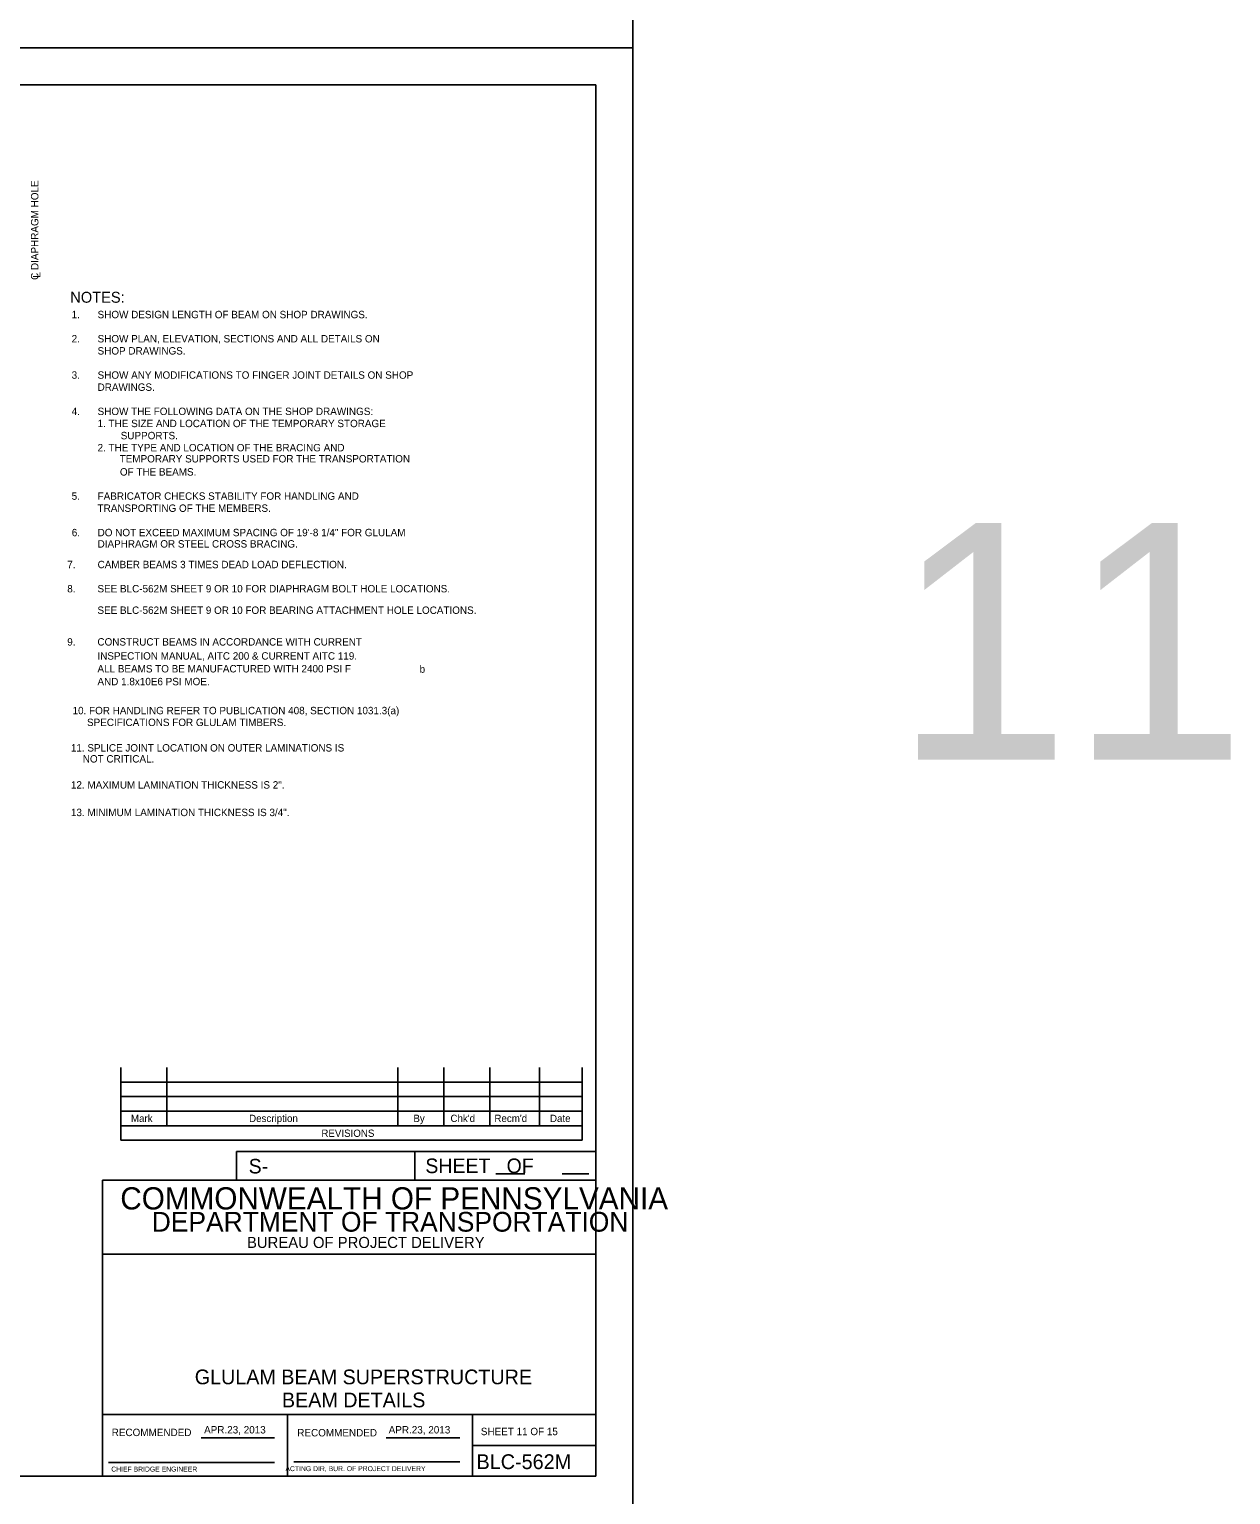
# Model space of a CAD drawing. Extents: x 638263 to 640391, y 293683 to 298655.
# Drawn here: x 639873 to 640360, y 296661 to 297255 of the extents above; entities that cross this region are included whole.
import ezdxf

# ---------------------------------------------------------------- set-up
doc = ezdxf.new("R2010")
doc.units = 0
for name, color, linetype in [('2', 7, 'Continuous'), ('4', 7, 'Continuous'), ('5', 7, 'Continuous'), ('PLT-BNDY', 7, 'Continuous')]:
    doc.layers.add(name, color=color, linetype=linetype)

msp = doc.modelspace()

# ---------------------------------------------------------------- linework, layer by layer
at = {"layer": '2'}
for p, q in [((639316.46, 297232.46), (640102.46, 297232.46)), ((640102.46, 297232.46), (640102.46, 296668.46)), ((639909.92, 296834.15), (639909.92, 296804.62)), ((639928.62, 296834.15), (639928.62, 296810.53)), ((640022.13, 296834.15), (640022.13, 296810.53)), ((640040.83, 296834.15), (640040.83, 296810.53)), ((640059.53, 296834.15), (640059.53, 296810.53)), ((640079.59, 296834.15), (640079.59, 296810.53)), ((640096.94, 296834.15), (640096.94, 296804.62)), ((640096.94, 296828.24), (639909.92, 296828.24)), ((640096.94, 296822.34), (639909.92, 296822.34)), ((640096.94, 296816.43), (639909.92, 296816.43)), ((640096.94, 296810.53), (639909.92, 296810.53)), ((640096.94, 296804.62), (639909.92, 296804.62)), ((640102.46, 296800.11), (639956.78, 296800.11)), ((639956.78, 296800.11), (639956.78, 296788.46)), ((640029.09, 296800.11), (640029.09, 296788.46)), ((640102.46, 296788.46), (639902.46, 296788.46)), ((639902.46, 296788.46), (639902.46, 296668.46)), ((640061.95, 296791), (640073.6, 296791)), ((640088.83, 296791), (640099.56, 296791)), ((640102.46, 296668.46), (640102.46, 296788.46)), ((640102.46, 296758.46), (639902.46, 296758.46)), ((640102.46, 296693.46), (639902.46, 296693.46)), ((639977.46, 296668.46), (639977.46, 296693.46)), ((640052.46, 296693.46), (640052.46, 296668.46)), ((639942.42, 296683.96), (639972.19, 296683.96)), ((640017.42, 296683.96), (640047.33, 296683.96)), ((640052.46, 296680.96), (640102.46, 296680.96)), ((639904.96, 296673.96), (639972.19, 296673.96)), ((639980.08, 296674.33), (640047.33, 296674.33)), ((640102.46, 296668.46), (639316.46, 296668.46)), ((639902.46, 296668.46), (640102.46, 296668.46))]:
    msp.add_line(p, q, dxfattribs=at)
at = {"layer": 'PLT-BNDY'}
for points in [[(639276.46, 297841.46), (640117.46, 297841.46), (640117.46, 297247.46), (639276.46, 297247.46)], [(639276.46, 297247.46), (640117.46, 297247.46), (640117.46, 296653.46), (639276.46, 296653.46)]]:
    msp.add_lwpolyline(points, close=True, dxfattribs=at)

# ---------------------------------------------------------------- texts
at = {"layer": '2'}
for s, height, p in [('Mark', 2.952, (639914.02, 296812.03)), ('Description', 2.9523, (639961.92, 296812.03)), ('By', 2.952, (640028.49, 296812.03)), ("Chk'd", 2.952, (640043.52, 296812.03)), ("Recm'd", 2.953, (640061.33, 296812.03)), ('Date', 2.952, (640083.86, 296812.03)), ('REVISIONS', 2.952, (639991.2, 296806.01)), ('S-', 5.905, (639961.73, 296791.17)), ('COMMONWEALTH OF PENNSYLVANIA', 9, (639909.71, 296776.58)), ('DEPARTMENT OF TRANSPORTATION', 8.0002, (639922.46, 296767.58)), ('BUREAU OF PROJECT DELIVERY', 4.5, (639961.05, 296760.96)), ('BEAM DETAILS', 5.9728, (639975.22, 296696.37)), ('APR.23, 2013', 3, (639943.67, 296685.77)), ('APR.23, 2013', 3, (640018.48, 296685.77)), ('SHEET 11 OF 15', 3, (640055.83, 296685.08)), ('BLC-562M', 6, (640054.08, 296671.33)), ('CHIEF BRIDGE ENGINEER', 2.0002, (639906.05, 296670.33)), ('  ACTING DIR, BUR. OF PROJECT DELIVERY', 2.0002, (639975.11, 296670.51))]:
    msp.add_text(s, height=height, dxfattribs=at).set_placement(p)
for s, height, p in [('SHEET   OF', 5.907, (640033.35, 296791.31)), ('RECOMMENDED', 3, (639906.23, 296684.71)), ('RECOMMENDED', 3, (639981.44, 296684.58))]:
    msp.add_text(s, height=height, rotation=360, dxfattribs=at).set_placement(p)
at = {"layer": '4'}
for s, height, p in [('11', 96, (640223.21, 296958.84)), ('GLULAM BEAM SUPERSTRUCTURE', 5.9728, (639939.89, 296705.71))]:
    msp.add_text(s, height=height, dxfattribs=at).set_placement(p)
at = {"layer": '5'}
for s, p in [('C DIAPHRAGM HOLE', (639876.52, 297153.37)), ('L', (639877.34, 297154.28))]:
    msp.add_text(s, height=3, rotation=90, dxfattribs=at).set_placement(p)
for s, height, p in [('NOTES:', 4.429, (639889.44, 297144.12)), ('1.', 3, (639889.99, 297137.84)), ('SHOW DESIGN LENGTH OF BEAM ON SHOP DRAWINGS.', 3, (639900.51, 297137.84)), ('2.', 3, (639889.99, 297128.03)), ('SHOW PLAN, ELEVATION, SECTIONS AND ALL DETAILS ON', 3, (639900.51, 297128.03)), ('SHOP DRAWINGS.', 3, (639900.51, 297123.12)), ('3.', 3, (639889.99, 297113.31)), ('SHOW ANY MODIFICATIONS TO FINGER JOINT DETAILS ON SHOP', 3, (639900.51, 297113.31)), ('DRAWINGS.', 3, (639900.51, 297108.41)), ('4.', 3, (639889.99, 297098.59)), ('SHOW THE FOLLOWING DATA ON THE SHOP DRAWINGS:', 3, (639900.51, 297098.59)), ('1. THE SIZE AND LOCATION OF THE TEMPORARY STORAGE', 3, (639900.51, 297093.69)), ('SUPPORTS.', 3, (639909.88, 297088.78)), ('2. THE TYPE AND LOCATION OF THE BRACING AND ', 3, (639900.51, 297083.88)), ('TEMPORARY SUPPORTS USED FOR THE TRANSPORTATION ', 3, (639909.46, 297079.38)), ('OF THE BEAMS.', 3, (639909.55, 297074.06)), ('5.', 3, (639889.99, 297064.25)), ('FABRICATOR CHECKS STABILITY FOR HANDLING AND ', 3, (639900.51, 297064.25)), ('TRANSPORTING OF THE MEMBERS.', 3, (639900.51, 297059.35)), ('6.', 3, (639890.04, 297049.47)), ('DO NOT EXCEED MAXIMUM SPACING OF 19\'-8 1/4" FOR GLULAM', 3, (639900.51, 297049.47)), ('DIAPHRAGM OR STEEL CROSS BRACING.', 3, (639900.51, 297044.87)), (' 7.', 3, (639887.09, 297036.51)), ('CAMBER BEAMS 3 TIMES DEAD LOAD DEFLECTION.', 3, (639900.51, 297036.51)), (' 8.', 3, (639887.09, 297026.7)), ('SEE BLC-562M SHEET 9 OR 10 FOR DIAPHRAGM BOLT HOLE LOCATIONS.', 3, (639900.45, 297026.71)), ('SEE BLC-562M SHEET 9 OR 10 FOR BEARING ATTACHMENT HOLE LOCATIONS.', 3, (639900.45, 297017.99)), (' 9.', 3, (639887.09, 297005.14)), ('CONSTRUCT BEAMS IN ACCORDANCE WITH CURRENT', 3, (639900.45, 297005.15)), ('INSPECTION MANUAL, AITC 200 & CURRENT AITC 119.', 3, (639900.45, 296999.45)), ('ALL BEAMS TO BE MANUFACTURED WITH 2400 PSI F', 3, (639900.45, 296994.26)), ('b', 3, (640031, 296994.11)), ('AND 1.8x10E6 PSI MOE.', 3, (639900.45, 296989.07)), ('10. FOR HANDLING REFER TO PUBLICATION 408, SECTION 1031.3(a)', 3, (639890.36, 296977.31)), ('   SPECIFICATIONS FOR GLULAM TIMBERS.', 3, (639892.88, 296972.53)), ('11. SPLICE JOINT LOCATION ON OUTER LAMINATIONS IS ', 3, (639889.69, 296962.2)), ('    NOT CRITICAL.', 3, (639890.05, 296957.74)), ('12. MAXIMUM LAMINATION THICKNESS IS 2".', 3, (639889.69, 296947.18)), ('13. MINIMUM LAMINATION THICKNESS IS 3/4".', 3, (639889.69, 296936.02))]:
    msp.add_text(s, height=height, dxfattribs=at).set_placement(p)

doc.saveas('drawing.dxf')
